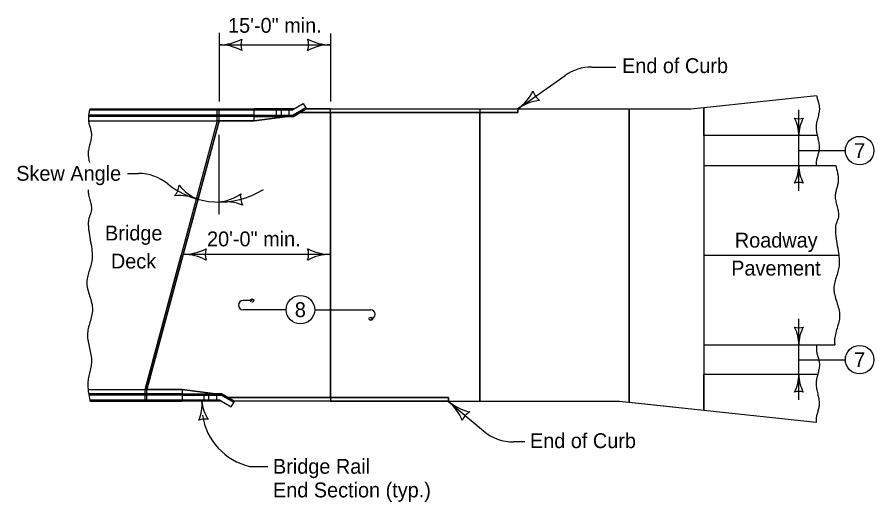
# Model space of a CAD drawing. Extents: x 5546 to 81668, y 3174 to 15999.
# Drawn here: x 18608 to 19530, y 8752 to 9275 of the extents above; entities that cross this region are included whole.
import ezdxf

# ---------------------------------------------------------------- set-up
doc = ezdxf.new("R2010")
doc.units = 0
for name, color, linetype in [('Annotation', 7, 'Continuous'), ('PS_BOLT', 7, 'Continuous'), ('PS_CONST', 7, 'Continuous'), ('PS_DIM', 7, 'Continuous'), ('Table Border', 7, 'Continuous')]:
    doc.layers.add(name, color=color, linetype=linetype)

msp = doc.modelspace()

# ---------------------------------------------------------------- linework, layer by layer
at = {"layer": 'Annotation'}
for p, q in [((18903.37, 9174.38), (18915.74, 9181.52)), ((18915.74, 9181.52), (18918.42, 9176.88)), ((18862.78, 9174.38), (18685.5, 9174.38)), ((18685.89, 9175.72), (18862.78, 9175.72)), ((18823, 9162.99), (18823, 9175.72)), ((18824.99, 9162.99), (18824.99, 9175.72)), ((18862.78, 9162.99), (18862.78, 9175.72)), ((18905.7, 9175.72), (18862.78, 9175.72)), ((18886.41, 9174.38), (18886.41, 9167.68)), ((18891.77, 9174.38), (18891.77, 9167.68)), ((18900.32, 9174.38), (18900.32, 9167.68)), ((18918.42, 9176.88), (18904.81, 9169.02)), ((18919.1, 9175.72), (18905.17, 9167.68)), ((18919.1, 9175.72), (18918.42, 9176.88)), ((18684.38, 9162.99), (18862.78, 9162.99)), ((18862.78, 9167.68), (18684.42, 9167.68)), ((18862.78, 9169.02), (18684.55, 9169.02)), ((18823, 9162.99), (18745.42, 8873.46)), ((18862.78, 9169.02), (18904.81, 9169.02)), ((18862.78, 9167.68), (18905.17, 9167.68)), ((18862.78, 9162.99), (18898.81, 9167.68)), ((18684.01, 8873.46), (18785.2, 8873.46)), ((18785.34, 8868.77), (18684.54, 8868.77)), ((18785.2, 8867.42), (18684.74, 8867.42)), ((18745.42, 8860.72), (18745.42, 8873.46)), ((18747.41, 8860.72), (18747.41, 8873.46)), ((18785.2, 8873.46), (18785.2, 8860.72)), ((18785.2, 8873.46), (18821.23, 8868.77)), ((18785.2, 8868.77), (18827.59, 8868.77)), ((18785.2, 8867.42), (18827.23, 8867.42)), ((18808.83, 8862.06), (18808.83, 8868.77)), ((18814.19, 8862.06), (18814.19, 8868.77)), ((18822.74, 8862.06), (18822.74, 8868.77)), ((18840.85, 8859.56), (18827.23, 8867.42)), ((18834.45, 8864.81), (18827.59, 8868.77)), ((18785.2, 8862.06), (18685.88, 8862.06)), ((18686.3, 8860.72), (18785.2, 8860.72)), ((18828.12, 8860.72), (18785.2, 8860.72)), ((18825.79, 8862.06), (18838.16, 8854.92)), ((18838.16, 8854.92), (18840.85, 8859.56)), ((18841.52, 8860.73), (18840.85, 8859.56))]:
    msp.add_line(p, q, dxfattribs=at)
for points in [[(18903.37, 9174.38), (18862.78, 9174.38), (18862.78, 9174.38), (18862.78, 9174.38)], [(18825.79, 8862.06), (18785.2, 8862.06), (18785.2, 8862.06), (18785.2, 8862.06)]]:
    msp.add_lwpolyline(points, dxfattribs=at)
at = {"layer": 'PS_CONST'}
for centre in [(18860.67, 8969.26), (18988.35, 8949.59)]:
    msp.add_circle(centre, 1.78, dxfattribs=at)
for centre, radius, start, end in [((18764.28, 8857.49), 42.5, 336.29398, 4.36647), ((18849.04, 8863.96), 42.5, 184.36647, 212.43895), ((18809.37, 8825.19), 16.42, 76.63311, 112.09982)]:
    msp.add_arc(centre, radius, start, end, dxfattribs=at)
at = {"layer": 'PS_DIM'}
for p, q in [((18824.99, 9257.53), (18824.99, 9183.59)), ((18945.06, 9256.8), (18945.06, 9183.59)), ((18824.99, 9244.76), (18945.06, 9244.76)), ((19226.51, 9220.7), (19252.26, 9220.7)), ((19146.63, 9175.72), (19197.79, 9211.62)), ((19347.18, 9177.21), (19468.53, 9190.24)), ((18685.89, 9175.72), (18685.89, 9175.72)), ((19449.48, 9087.36), (19449.48, 9174.78)), ((18824.99, 9062.36), (18824.99, 9147.74)), ((19469.3, 9146.9), (19347.18, 9146.9)), ((19449.48, 9130.77), (19478.95, 9130.77)), ((19478.95, 9130.77), (19499.51, 9130.77)), ((19347.18, 9114.73), (19489.28, 9114.73)), ((18726.48, 9106.13), (18738.27, 9106.13)), ((18945.06, 9018.99), (18786.4, 9018.99)), ((19347.18, 9018.22), (19492.49, 9018.22)), ((18860.67, 8969.26), (18850.84, 8969.26)), ((18897.33, 8959.43), (18850.85, 8959.43)), ((18928.05, 8959.43), (18988.35, 8959.43)), ((19449.48, 8862.17), (19449.48, 8949.6)), ((19347.18, 8921.71), (19488.14, 8921.71)), ((19449.48, 8905.58), (19478.95, 8905.58)), ((19478.95, 8905.58), (19499.51, 8905.58)), ((19469.74, 8889.54), (19347.18, 8889.54)), ((18685.95, 8861.81), (18686.3, 8860.72)), ((19072.22, 8860.7), (19109.93, 8828.78)), ((19468.15, 8837.91), (19347.18, 8850.9)), ((19154.51, 8816.94), (19142.24, 8816.94)), ((18857.99, 8790.62), (18877.5, 8790.62))]:
    msp.add_line(p, q, dxfattribs=at)
for points in [[(18945.06, 8864.79), (18834.45, 8864.81), (18827.6, 8868.77), (18822.74, 8868.77), (18821.23, 8868.77), (18785.21, 8873.46), (18747.41, 8873.46), (18824.99, 9162.99), (18862.79, 9162.99), (18898.81, 9167.68), (18905.17, 9167.68), (18905.18, 9167.68), (18910.51, 9170.76), (18912.13, 9171.7), (18945.06, 9171.7)], [(19146.63, 9175.74), (19146.63, 9171.7), (18912.13, 9171.7), (18919.09, 9175.72)], [(19146.63, 9171.7), (19146.63, 9175.72), (19266.76, 9175.72), (19266.76, 8859.54), (19256.29, 8860.66), (19105.91, 8860.69), (19105.91, 9171.7)], [(19347.18, 9177.21), (19347.18, 8850.9), (19266.76, 8859.54), (19266.76, 9175.72), (19333.26, 9175.72)], [(19072.22, 8864.77), (19072.22, 8860.72), (18841.52, 8860.73), (18834.45, 8864.81)]]:
    msp.add_lwpolyline(points, close=True, dxfattribs=at)
msp.add_lwpolyline([(19072.22, 8860.7), (19072.22, 8864.77), (18945.06, 8864.79), (18945.06, 9171.7), (19105.91, 9171.7), (19105.91, 8860.69), (19072.22, 8860.7)], dxfattribs=at)
for centre in [(19514.87, 9130.77), (18912.69, 8959.43), (18912.69, 8959.43), (19514.87, 8905.58)]:
    msp.add_circle(centre, 15.36, dxfattribs=at)
for centre, radius, start, end in [((18824.99, 9296.98), 52.23, 270, 298.07249), ((18868.78, 9244.75), 20.17, 162.26665, 197.73335), ((18901.26, 9244.75), 20.17, 342.26665, 17.73335), ((18945.06, 9296.98), 52.23, 241.92751, 270), ((18824.99, 9192.52), 52.23, 61.92751, 90), ((18945.06, 9192.52), 52.23, 90, 118.07249), ((19226.51, 9170.7), 50, 90, 125.06176), ((19116.63, 9218.47), 52.23, 305.06176, 333.13425), ((19182.47, 9200.87), 20.17, 197.32841, 232.79511), ((19176.63, 9132.97), 52.23, 96.98927, 125.06176), ((19449.48, 9180.59), 15.52, 252.26665, 287.73335), ((19409.31, 9146.9), 40.18, 360, 28.07249), ((19489.66, 9146.9), 40.18, 151.92751, 180), ((19409.31, 9114.73), 40.18, 331.92751, 360), ((19489.66, 9114.73), 40.18, 180, 208.07249), ((18738.27, 9056.13), 50, 51.03773, 90), ((18825.49, 9163.98), 88.71, 231.03773, 302.32505), ((18761.85, 9095.12), 20.17, 319.76199, 355.22869), ((18822.3, 9126.6), 52.23, 219.42285, 247.49534), ((19449.48, 9081.05), 15.52, 72.26665, 107.73335), ((18782.32, 9030.1), 52.23, 67.49534, 95.56783), ((18818.79, 9127.13), 52.23, 276.80986, 304.88235), ((18868.47, 9080.46), 20.17, 169.07651, 204.54321), ((18831.18, 9023.41), 52.23, 68.73737, 96.80986), ((18786.42, 9071.21), 52.23, 270, 298.07249), ((18830.21, 9018.99), 20.17, 162.26665, 197.73335), ((18901.26, 9018.99), 20.17, 342.26665, 17.73335), ((18945.06, 9071.21), 52.23, 241.92751, 270), ((18786.42, 8966.76), 52.23, 61.92751, 90), ((18945.06, 8966.76), 52.23, 90, 118.07249), ((18850.84, 8964.34), 4.92, 90, 270), ((18988.35, 8954.51), 4.92, 270, 90), ((19449.48, 8955.4), 15.52, 252.26665, 287.73335), ((19409.31, 8921.71), 40.18, 360, 28.07249), ((19489.66, 8921.71), 40.18, 151.92751, 180), ((19409.31, 8889.54), 40.18, 331.92751, 360), ((19489.66, 8889.54), 40.18, 180, 208.07249), ((19449.48, 8855.86), 15.52, 72.26665, 107.73335), ((19038.47, 8820.84), 52.23, 21.68043, 49.75292), ((19105.96, 8900.57), 52.23, 229.75292, 257.82541), ((19038.47, 8820.84), 52.23, 49.75179, 49.75293), ((19105.64, 8832.41), 20.17, 122.01957, 157.48627), ((18873.12, 8855.55), 66.66, 188.48278, 256.88228), ((19142.24, 8866.94), 50, 229.75292, 270)]:
    msp.add_arc(centre, radius, start, end, dxfattribs=at)
for points in [[(18685.89, 9175.72), (18684.77, 9170.71), (18684.47, 9168.19), (18684.29, 9165.67), (18684.67, 9161.23), (18685.82, 9156.79), (18687.04, 9152.35), (18687.6, 9147.9), (18687.06, 9142.81), (18685.85, 9137.72), (18684.63, 9132.62), (18684.22, 9130.07), (18684.05, 9127.52), (18684.44, 9122.81), (18685.38, 9118.09)], [(18684.04, 9088.39), (18684.6, 9083.14), (18685.9, 9077.87), (18687.16, 9072.6), (18687.6, 9067.34), (18687.04, 9064.12), (18685.96, 9060.94), (18684.87, 9057.76), (18684.29, 9054.55), (18684.29, 9049.64), (18684.72, 9044.7), (18686.31, 9034.74), (18687.91, 9024.8), (18688.44, 9017.41), (18688.4, 9014.97), (18687.37, 9008.55), (18685.46, 9002.14), (18683.58, 8995.73), (18682.61, 8989.3), (18682.79, 8985.55), (18683.46, 8981.79), (18685.63, 8974.29), (18687.83, 8966.79), (18688.76, 8959.28), (18688.48, 8955.94), (18687.84, 8952.6), (18685.99, 8945.91), (18684.17, 8939.22), (18683.33, 8932.53), (18684.03, 8925.32), (18685.56, 8918.08), (18687.07, 8910.84), (18687.67, 8903.6), (18686.94, 8897.36), (18685.49, 8891.12), (18684.15, 8884.89), (18683.69, 8878.65), (18683.94, 8874.43), (18684.35, 8870.2), (18685.95, 8861.81)]]:
    msp.add_spline(points, degree=3, dxfattribs=at)
at = {"layer": 'Table Border'}
for p, q in [((18919.09, 9175.72), (18905.18, 9167.68)), ((18912.13, 9171.7), (19146.63, 9171.7)), ((18945.06, 9175.72), (18919.09, 9175.72)), ((18945.06, 9018.22), (18945.06, 9175.72)), ((18945.06, 9175.72), (19105.91, 9175.72)), ((19105.91, 9175.72), (19105.91, 9018.22)), ((19105.91, 9175.72), (19333.26, 9175.72)), ((19146.63, 9175.72), (19146.63, 9171.7)), ((19266.76, 9175.72), (19266.76, 8859.54)), ((19333.26, 9175.72), (19347.18, 9177.21)), ((19347.18, 9146.9), (19347.18, 9177.21)), ((19347.18, 9177.21), (19347.18, 9018.22)), ((18824.99, 9162.99), (18747.41, 8873.46)), ((18823, 9162.99), (18784.21, 9018.22)), ((18862.79, 9162.99), (18823, 9162.99)), ((18898.81, 9167.68), (18862.79, 9162.99)), ((18905.18, 9167.68), (18898.81, 9167.68)), ((19347.18, 9146.9), (19347.18, 9114.73)), ((18745.42, 8873.46), (18784.21, 9018.22)), ((18945.06, 9018.22), (18945.06, 8860.73)), ((19105.91, 8860.69), (19105.91, 9018.22)), ((19347.18, 9018.22), (19347.18, 8850.9)), ((19347.18, 8850.9), (19347.18, 8889.54)), ((18785.21, 8873.46), (18745.42, 8873.46)), ((18821.23, 8868.77), (18785.21, 8873.46)), ((18827.6, 8868.77), (18821.23, 8868.77)), ((18841.51, 8860.73), (18827.6, 8868.77)), ((18834.45, 8864.81), (19072.22, 8864.74)), ((18945.06, 8860.73), (18841.51, 8860.73)), ((18945.06, 8860.73), (19105.91, 8860.69)), ((19072.22, 8860.7), (19072.22, 8864.74)), ((19256.29, 8860.66), (19105.91, 8860.69)), ((19347.18, 8850.9), (19256.29, 8860.66))]:
    msp.add_line(p, q, dxfattribs=at)
for points in [[(19468.53, 9190.24), (19469.34, 9186.74), (19470.36, 9183.23), (19471.23, 9179.72), (19471.6, 9176.21), (19471.05, 9171.12), (19469.84, 9166.03), (19468.62, 9160.93), (19468.04, 9155.84), (19468.55, 9150.39), (19469.72, 9144.94), (19470.87, 9139.48), (19471.36, 9134.04), (19470.84, 9129.76), (19469.74, 9125.5), (19468.63, 9121.24), (19468.04, 9116.98), (19468.09, 9114.73)], [(19489.28, 9114.73), (19491, 9106.96), (19491.69, 9103.07), (19491.94, 9099.2), (19491.42, 9094.92), (19490.32, 9090.66), (19489.21, 9086.4), (19488.62, 9082.14), (19489.13, 9076.82), (19490.44, 9071.48), (19491.72, 9066.14), (19492.18, 9060.81), (19491.61, 9057.59), (19490.53, 9054.41), (19489.45, 9051.23), (19488.86, 9048.02), (19488.86, 9043.11), (19489.3, 9038.17), (19490.88, 9028.22), (19492.48, 9018.27), (19493.01, 9010.88), (19492.97, 9008.44), (19491.94, 9002.02), (19490.04, 8995.61), (19488.15, 8989.2), (19487.18, 8982.77), (19487.36, 8979.02), (19488.03, 8975.27), (19490.21, 8967.76), (19492.4, 8960.26), (19493.33, 8952.76), (19493.05, 8949.41), (19492.42, 8946.07), (19490.56, 8939.39), (19488.74, 8932.7), (19487.91, 8926), (19488.14, 8921.71)], [(19468.6, 8921.71), (19468.28, 8917.93), (19468.66, 8913.48), (19469.82, 8909.04), (19471.03, 8904.6), (19471.6, 8900.16), (19471.05, 8895.07), (19469.84, 8889.97), (19468.62, 8884.88), (19468.04, 8879.78), (19468.55, 8874.34), (19469.72, 8868.88), (19470.87, 8863.42), (19471.36, 8857.98), (19470.84, 8853.71), (19469.74, 8849.45), (19468.63, 8845.19), (19468.04, 8840.92), (19468.15, 8837.91)]]:
    msp.add_spline(points, degree=3, dxfattribs=at)

# ---------------------------------------------------------------- texts
at = {"layer": 'PS_BOLT'}
for s, p in [('15\'-0" min.', (18834.75, 9257.68)), ('End of Curb', (19259.01, 9214.28)), ('7', (19508.99, 9122.77)), ('Skew Angle', (18606.61, 9098.3)), ('Bridge', (18702.22, 9033.98)), ('20\'-0" min.', (18812.08, 9027.66)), ('Roadway', (19380.49, 9026.35)), ('Deck', (18708.56, 9003.8)), ('Pavement', (19376.6, 8996.17)), ('8', (18906.66, 8951.42)), ('7', (19508.99, 8897.58)), ('End of Curb', (19159.84, 8810.31))]:
    msp.add_text(s, height=16, dxfattribs=at).set_placement(p)
at = {"layer": 'PS_DIM'}
for s, p in [('Bridge Rail', (18883.1, 8782.71)), ('End Section (typ.)', (18883.1, 8757.26))]:
    msp.add_text(s, height=16, dxfattribs=at).set_placement(p)

doc.saveas('drawing.dxf')
